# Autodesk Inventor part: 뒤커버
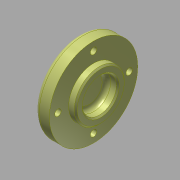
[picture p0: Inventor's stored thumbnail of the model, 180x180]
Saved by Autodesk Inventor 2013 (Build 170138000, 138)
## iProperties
Created: 2015-12
Part Number: 뒤커버
Document SubType Name: Modeling
Designer: mdu
Density: 2.71 g/cm^3
Material: 알루미늄 6061
Mass: 80.8108 g
Surface Area: 93.036 cm^2
Volume: 29.8195 cm^3
Author: mdu
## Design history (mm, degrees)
sketch "스케치1"
  geometry: L1 (-7.5, 0)-(7.5, 0); L2 (-7.5, 0)-(-7.5, 31); L3 (-7.5, 31)-(2.5, 31); L4 (2.5, 31)-(2.5, 17.5); L5 (2.5, 17.5)-(7.5, 17.5); L6 (7.5, 17.5)-(7.5, 0); 2 further points
  constraints: 12 end point, 3 parallel, 1 coincident, 1 horizontal, 1 midpoint, 1 perpendicular
  dimensions: "d0" = 15 distance of L1.start L1.end; "d1" = 62 diameter of L3 L1; "d2" = 35 diameter of L5 L1; "d34" = 10 distance of L2.end L3.end
revolve "회전1" sketch "스케치1" stored, may be unused: angle "d6" = 90 deg
sketch "스케치2" dims "d32" = 50
  geometry: 3 further points
  constraints: 2 vertical alignment, 1 coincident, 2 other
hole "구멍1" sketch "스케치2" at (0, 25) diameter "d8" = 4.5; stored, may be unused: countersink angle "d12" = 90 deg, drill point angle "d14" = 118 deg; dims "d9" = 6, "d10" = 8, "d11" = 4.4, "d13" = 8
hole "구멍2" diameter "d20" = 24; stored, may be unused: countersink angle "d24" = 90 deg, drill point angle "d26" = 0 deg; dims "d18" = 10, "d19" = 10, "d21" = 6, "d22" = 8, "d23" = 4.4, "d25" = 8
fillet "모깎기1" dims "d27" = 3
fillet "모깎기2" dims "d28" = 3
chamfer "모따기1" distance "d29" = 1; stored, may be unused: second distance "d30" = 2, angle "d31" = 45 deg
node "솔리드1"
pattern_circular "원형 패턴1" dims angle "d16" = 360 deg
